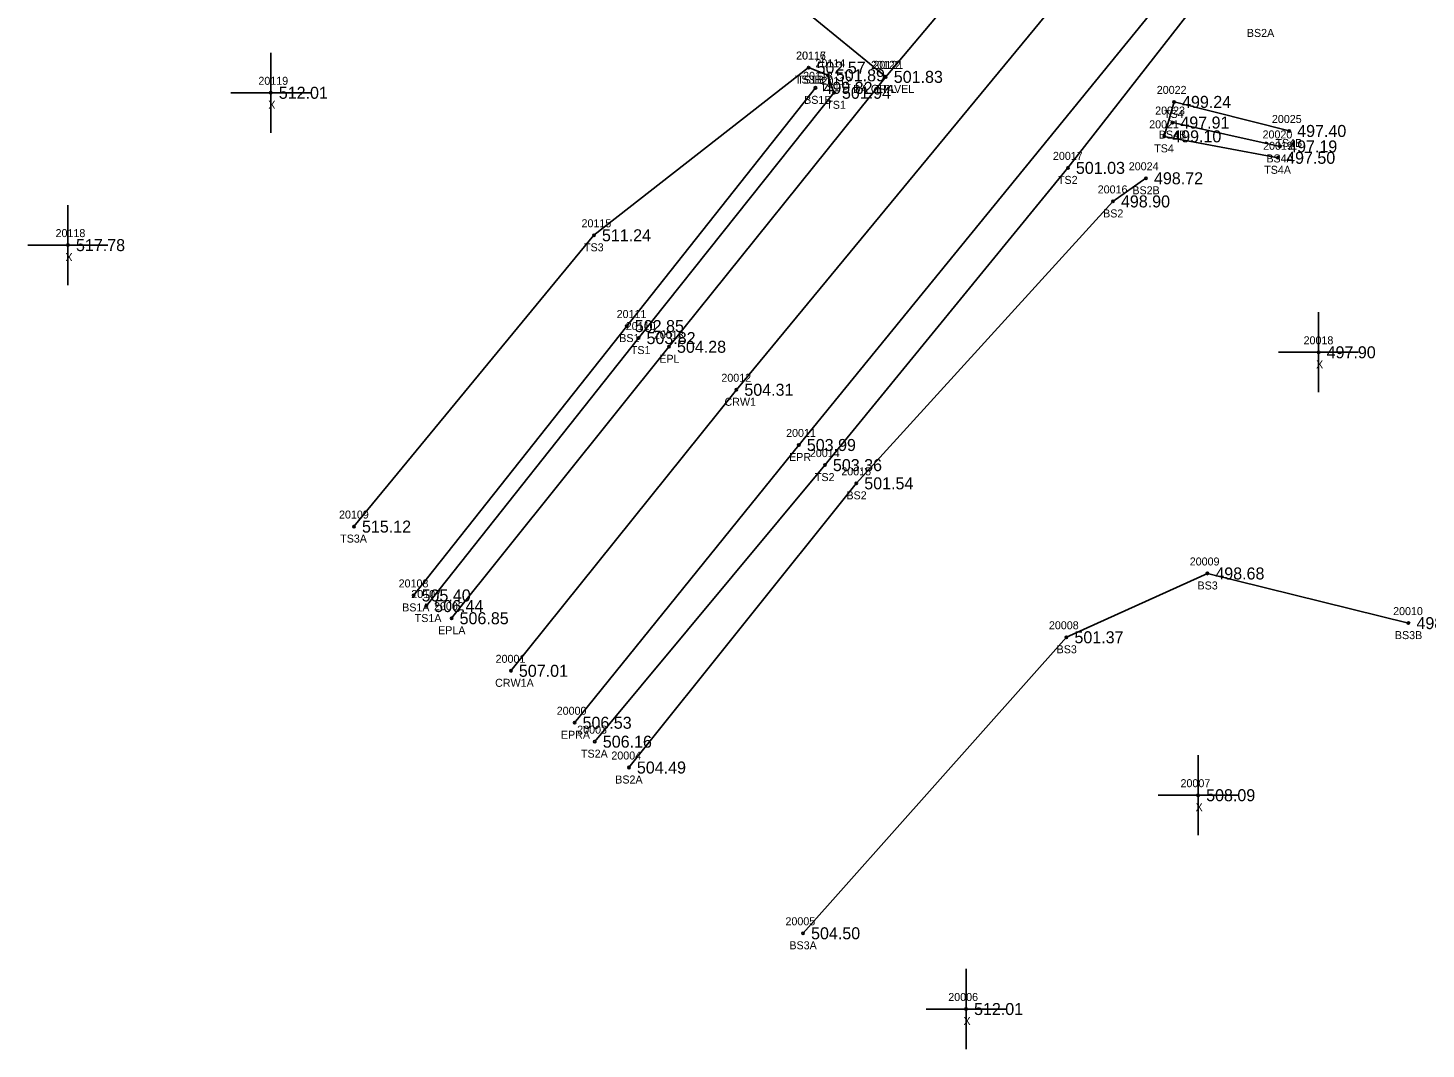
# Model space of a CAD drawing. Extents: x 1649406 to 1650436, y 896752 to 898178.
# Drawn here: x 1649406.4 to 1649581.2, y 896751.9 to 896879.4 of the extents above; entities that cross this region are included whole.
import ezdxf

# ---------------------------------------------------------------- set-up
doc = ezdxf.new("R2010")
doc.units = 0
for name, color, linetype in [('RD_DTM_BkLn1', 7, 'Continuous'), ('RD_DTM_BkLn2', 7, 'Continuous'), ('RD_DTM_BkLn_txCode', 7, 'Continuous'), ('RD_EX_Driveway', 7, 'Continuous'), ('RD_EX_Driveway_txCode', 7, 'Continuous'), ('RD_EX_Misc', 7, 'Continuous'), ('RD_EX_Misc_txCode', 7, 'Continuous'), ('RD_EX_Road', 7, 'Continuous'), ('RD_EX_Road_txCode', 7, 'Continuous'), ('RD_EX_TX_Driveway_ELEV', 7, 'Continuous'), ('RD_EX_TX_Misc_ELEV', 7, 'Continuous'), ('RD_EX_TX_Road_ELEV', 7, 'Continuous'), ('RD_HC_Survey_ELEV', 7, 'Continuous'), ('RD_HC_Survey_txCode', 7, 'Continuous'), ('RD_SMD_Locator', 7, 'Continuous')]:
    doc.layers.add(name, color=color, linetype=linetype)

msp = doc.modelspace()

# ---------------------------------------------------------------- linework, layer by layer
at = {"layer": 'RD_DTM_BkLn1'}
msp.add_lwpolyline([(1649466.79, 896799.14), (1649494.97, 896834.25), (1649557.53, 896909.97), (1649590.88, 896950.41), (1649622.36, 896988.16), (1649622.36, 896988.48), (1649654.33, 897027.92), (1649685.38, 897067.52), (1649715.96, 897107.48), (1649743.64, 897146.32), (1649771.01, 897187.23), (1649797.64, 897230.08), (1649820.89, 897273.98), (1649842.91, 897321.22), (1649862.74, 897368.05), (1649877.08, 897408.66)], dxfattribs=at)
at = {"layer": 'RD_DTM_BkLn2'}
msp.add_line((1649562.94, 896864.65), (1649549.47, 896867.63), dxfattribs=at)
for points in [[(1649477.28, 896790.29), (1649506.04, 896824.84), (1649536.41, 896861.97), (1649567.77, 896902.18), (1649602.54, 896939.62), (1649634.46, 896978.81), (1649648.91, 896984.68)], [(1649447.18, 896817.16), (1649477.17, 896853.55), (1649504, 896874.5)], [(1649456.21, 896807.23), (1649482.74, 896840.71), (1649507.17, 896871.35), (1649506.41, 896873.54), (1649504, 896874.5)], [(1649454.63, 896808.56), (1649481.28, 896842.21), (1649504.86, 896871.97)], [(1649562.69, 896863.23), (1649548.45, 896865.91), (1649549.68, 896870.21), (1649564.07, 896866.58)], [(1649481.54, 896787.06), (1649509.96, 896822.56), (1649542.04, 896857.78), (1649546.17, 896860.67)], [(1649503.31, 896766.35), (1649536.23, 896803.33), (1649553.84, 896811.3), (1649578.98, 896805.1)]]:
    msp.add_lwpolyline(points, dxfattribs=at)
at = {"layer": 'RD_EX_Driveway'}
msp.add_line((1649513.65, 896873.34), (1649490.46, 896892.31), dxfattribs=at)
at = {"layer": 'RD_EX_Misc'}
for p, q in [((1649436.78, 896866.35), (1649436.78, 896876.35)), ((1649431.78, 896871.35), (1649441.78, 896871.35)), ((1649411.43, 896847.32), (1649411.43, 896857.32)), ((1649406.43, 896852.32), (1649416.43, 896852.32)), ((1649567.75, 896833.93), (1649567.75, 896843.93)), ((1649562.75, 896838.93), (1649572.75, 896838.93)), ((1649552.69, 896778.6), (1649552.69, 896788.6)), ((1649547.69, 896783.6), (1649557.69, 896783.6)), ((1649523.68, 896751.89), (1649523.68, 896761.89)), ((1649518.68, 896756.89), (1649528.68, 896756.89))]:
    msp.add_line(p, q, dxfattribs=at)
at = {"layer": 'RD_EX_Road'}
for points in [[(1649459.38, 896805.71), (1649486.55, 896839.62), (1649513.65, 896873.34), (1649538.22, 896902.56), (1649549.43, 896916.62), (1649583.1, 896957.27), (1649614.8, 896995.02), (1649647.06, 897035.69), (1649677.62, 897074.51), (1649708.33, 897114.44), (1649735.5, 897151.61), (1649762.11, 897192.19), (1649788.21, 897235.29), (1649812.17, 897279.73), (1649834.32, 897326.54), (1649852.94, 897371.82), (1649867.51, 897411.96)], [(1649474.75, 896792.65), (1649502.78, 896827.35), (1649565.2, 896903.92), (1649598.28, 896943.71), (1649629.8, 896982.26), (1649667.92, 897029.33), (1649693.13, 897061.44), (1649723.58, 897101.84), (1649752.37, 897141.09), (1649779.72, 897182.3), (1649806.12, 897225.84), (1649830.13, 897270.79), (1649852.39, 897317.43), (1649871.98, 897364.35), (1649886.55, 897406.09)]]:
    msp.add_lwpolyline(points, dxfattribs=at)
at = {"layer": 'RD_SMD_Locator'}
for centre in [(1649504, 896874.5), (1649504, 896874.5), (1649506.41, 896873.54), (1649513.65, 896873.34), (1649513.65, 896873.34), (1649436.78, 896871.35), (1649504.86, 896871.97), (1649507.17, 896871.35), (1649549.68, 896870.21), (1649548.45, 896865.91), (1649549.47, 896867.63), (1649564.07, 896866.58), (1649562.94, 896864.65), (1649562.69, 896863.23), (1649536.41, 896861.97), (1649546.17, 896860.67), (1649542.04, 896857.78), (1649411.43, 896852.32), (1649477.17, 896853.55), (1649481.28, 896842.21), (1649482.74, 896840.71), (1649486.55, 896839.62), (1649567.75, 896838.93), (1649494.97, 896834.25), (1649502.78, 896827.35), (1649506.04, 896824.84), (1649509.96, 896822.56), (1649447.18, 896817.16), (1649553.84, 896811.3), (1649454.63, 896808.56), (1649456.21, 896807.23), (1649459.38, 896805.71), (1649578.98, 896805.1), (1649536.23, 896803.33), (1649466.79, 896799.14), (1649474.75, 896792.65), (1649477.28, 896790.29), (1649481.54, 896787.06), (1649552.69, 896783.6), (1649503.31, 896766.35), (1649523.68, 896756.89)]:
    msp.add_circle(centre, 0.15, dxfattribs=at)

# ---------------------------------------------------------------- texts
at = {"layer": 'RD_DTM_BkLn_txCode'}
for s, p in [('BS2A', (1649558.78, 896878.33)), ('20116', (1649502.43, 896875.5)), ('20117', (1649502.45, 896875.5)), ('20114', (1649504.86, 896874.54)), ('TS3B', (1649502.29, 896872.5)), ('TS1B', (1649502.57, 896872.5)), ('20113', (1649503.31, 896872.97)), ('20112', (1649505.62, 896872.35)), ('TS1', (1649505.45, 896871.54)), ('20022', (1649547.52, 896871.21)), ('BS1B', (1649503.44, 896869.97)), ('TS1', (1649506.21, 896869.35)), ('20023', (1649547.32, 896868.63)), ('20021', (1649546.57, 896866.91)), ('TS4', (1649548.43, 896868.21)), ('20025', (1649561.91, 896867.58)), ('BS4B', (1649547.77, 896865.63)), ('20020', (1649560.74, 896865.65)), ('TS4', (1649547.2, 896863.91)), ('20019', (1649560.81, 896864.23)), ('TS4B', (1649562.35, 896864.58)), ('20017', (1649534.54, 896862.97)), ('20024', (1649544.02, 896861.67)), ('BS4A', (1649561.22, 896862.65)), ('TS2', (1649535.17, 896859.97)), ('TS4A', (1649560.95, 896861.23)), ('20016', (1649540.14, 896858.78)), ('BS2B', (1649544.47, 896858.67)), ('20115', (1649475.62, 896854.55)), ('BS2', (1649540.81, 896855.78)), ('TS3', (1649475.93, 896851.55)), ('20111', (1649480.01, 896843.21)), ('20110', (1649481.15, 896841.71)), ('BS1', (1649480.33, 896840.21)), ('TS1', (1649481.78, 896838.71)), ('20014', (1649504.16, 896825.84)), ('20015', (1649508.09, 896823.56)), ('TS2', (1649504.79, 896822.84)), ('BS2', (1649508.73, 896820.56)), ('20109', (1649445.31, 896818.16)), ('TS3A', (1649445.45, 896815.16)), ('20009', (1649551.64, 896812.3)), ('20108', (1649452.76, 896809.56)), ('BS3', (1649552.61, 896809.3)), ('20107', (1649454.34, 896808.23)), ('BS1A', (1649453.2, 896806.56)), ('20010', (1649577.06, 896806.1)), ('TS1A', (1649454.77, 896805.23)), ('20008', (1649534.04, 896804.33)), ('BS3B', (1649577.28, 896803.1)), ('BS3', (1649535, 896801.33)), ('20003', (1649475.08, 896791.29)), ('TS2A', (1649475.55, 896788.29)), ('20004', (1649479.35, 896788.06)), ('BS2A', (1649479.83, 896785.06)), ('20005', (1649501.11, 896767.35)), ('BS3A', (1649501.6, 896764.35))]:
    msp.add_text(s, height=1, dxfattribs=at).set_placement(p)
at = {"layer": 'RD_EX_Driveway_txCode'}
for s, p in [('20122', (1649511.81, 896874.34)), ('DA GRAVEL', (1649509.55, 896871.34))]:
    msp.add_text(s, height=1, dxfattribs=at).set_placement(p)
at = {"layer": 'RD_EX_Misc_txCode'}
for s, p in [('20119', (1649435.23, 896872.35)), ('X', (1649436.47, 896869.35)), ('20118', (1649409.88, 896853.32)), ('X', (1649411.11, 896850.32)), ('20018', (1649565.87, 896839.93)), ('X', (1649567.43, 896836.93)), ('20007', (1649550.49, 896784.6)), ('X', (1649552.37, 896781.6)), ('20006', (1649521.46, 896757.89)), ('X', (1649523.36, 896754.89))]:
    msp.add_text(s, height=1, dxfattribs=at).set_placement(p)
at = {"layer": 'RD_EX_Road_txCode'}
for s, p in [('20121', (1649512.1, 896874.34)), ('EPL', (1649512.44, 896871.34)), ('20013', (1649484.67, 896840.62)), ('EPL', (1649485.34, 896837.62)), ('20011', (1649501.19, 896828.35)), ('EPR', (1649501.56, 896825.35)), ('20002', (1649457.18, 896806.71)), ('EPLA', (1649457.69, 896803.71)), ('20000', (1649472.52, 896793.65)), ('EPRA', (1649473.04, 896790.65))]:
    msp.add_text(s, height=1, dxfattribs=at).set_placement(p)
at = {"layer": 'RD_EX_TX_Driveway_ELEV'}
msp.add_text('501.83', height=1.5, dxfattribs=at).set_placement((1649514.65, 896872.59))
at = {"layer": 'RD_EX_TX_Misc_ELEV'}
for s, p in [('502.57', (1649505, 896873.75)), ('502.57', (1649505, 896873.75)), ('501.89', (1649507.41, 896872.79)), ('512.01', (1649437.78, 896870.6)), ('499.82', (1649505.86, 896871.22)), ('501.94', (1649508.17, 896870.6)), ('499.24', (1649550.68, 896869.46)), ('497.91', (1649550.47, 896866.88)), ('499.10', (1649549.45, 896865.16)), ('497.40', (1649565.07, 896865.83)), ('497.19', (1649563.94, 896863.9)), ('501.03', (1649537.41, 896861.22)), ('497.50', (1649563.69, 896862.48)), ('498.72', (1649547.17, 896859.92)), ('498.90', (1649543.04, 896857.03)), ('511.24', (1649478.17, 896852.8)), ('517.78', (1649412.43, 896851.57)), ('502.85', (1649482.28, 896841.46)), ('503.82', (1649483.74, 896839.96)), ('497.90', (1649568.75, 896838.18)), ('503.36', (1649507.04, 896824.09)), ('501.54', (1649510.96, 896821.81)), ('515.12', (1649448.18, 896816.41)), ('498.68', (1649554.84, 896810.55)), ('505.40', (1649455.63, 896807.81)), ('506.44', (1649457.21, 896806.48)), ('498.04', (1649579.98, 896804.35)), ('501.37', (1649537.23, 896802.58)), ('506.16', (1649478.28, 896789.54)), ('504.49', (1649482.54, 896786.31)), ('508.09', (1649553.69, 896782.85)), ('504.50', (1649504.31, 896765.6)), ('512.01', (1649524.68, 896756.14))]:
    msp.add_text(s, height=1.5, dxfattribs=at).set_placement(p)
at = {"layer": 'RD_EX_TX_Road_ELEV'}
for s, p in [('501.83', (1649514.65, 896872.59)), ('504.28', (1649487.55, 896838.87)), ('503.99', (1649503.78, 896826.6)), ('506.85', (1649460.38, 896804.96)), ('506.53', (1649475.75, 896791.9))]:
    msp.add_text(s, height=1.5, dxfattribs=at).set_placement(p)
at = {"layer": 'RD_HC_Survey_ELEV'}
for s, p in [('504.31', (1649495.97, 896833.5)), ('507.01', (1649467.79, 896798.39))]:
    msp.add_text(s, height=1.5, dxfattribs=at).set_placement(p)
at = {"layer": 'RD_HC_Survey_txCode'}
for s, p in [('20012', (1649493.1, 896835.25)), ('CRW1', (1649493.49, 896832.25)), ('20001', (1649464.88, 896800.14)), ('CRW1A', (1649464.82, 896797.14))]:
    msp.add_text(s, height=1, dxfattribs=at).set_placement(p)

doc.saveas('drawing.dxf')
